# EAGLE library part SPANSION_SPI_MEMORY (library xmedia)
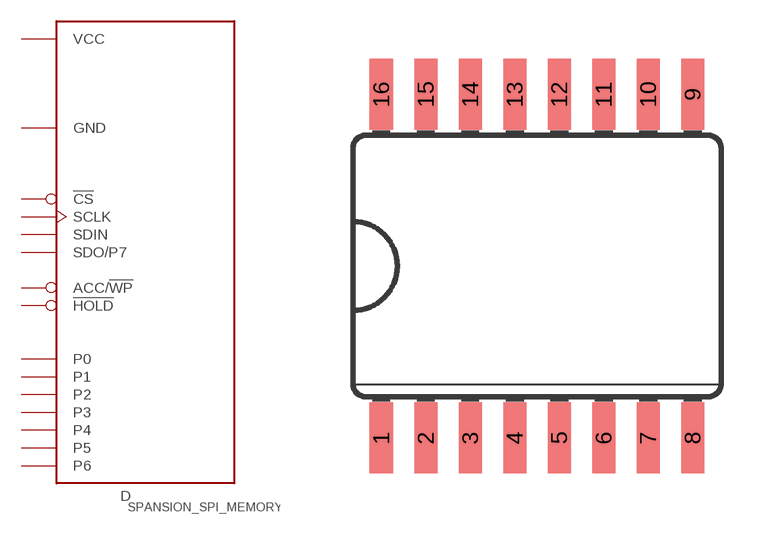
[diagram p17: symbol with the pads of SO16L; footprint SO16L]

Designator prefix D

## SPANSION_SPI_MEMORY  [SO16L]
1  !HOLD
2  VCC  sup
4  P2
5  P1
6  P0
7  !CS  in
8  SDO/P7  out
9  ACC/!WP!
10  GND  sup
11  P3
12  P4
13  P5
14  P6
15  SDIN  in
16  SCLK  in

## Footprint SO16L (pad centres in mm)
Small Outline Package .300 SIOC Source: http://www.maxim-ic.com/cgi-bin/packages?pkg=16%2FSOIC%2E300&Type=Max
smd 0.66 x 2.032: 1 -4.445,-4.902; 2 -3.175,-4.902; 3 -1.905,-4.902; 4 -0.635,-4.902; 5 0.635,-4.902; 6 1.905,-4.902; 7 3.175,-4.902; 8 4.445,-4.902; 9 4.445,4.902; 10 3.175,4.902; 11 1.905,4.902; 12 0.635,4.902; 13 -0.635,4.902; 14 -1.905,4.902; 15 -3.175,4.902; 16 -4.445,4.902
